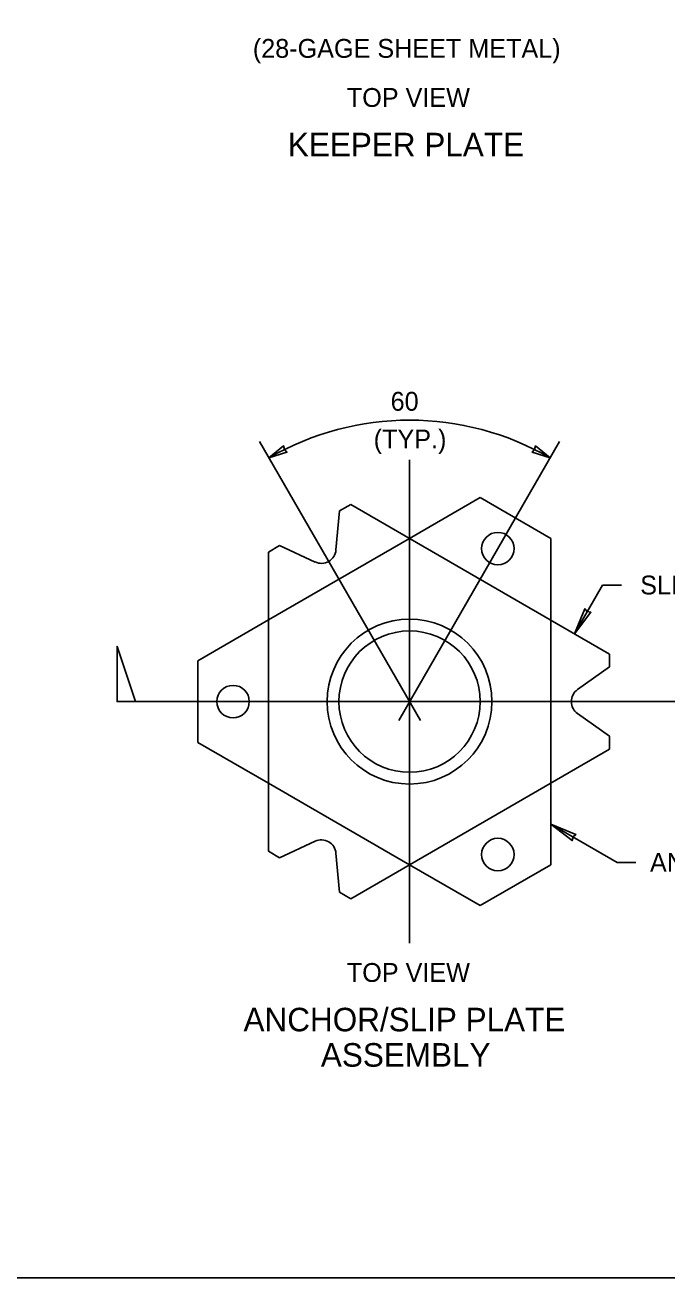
# Model space of a CAD drawing. Extents: x 99862 to 104211, y 98939 to 102076.
# Drawn here: x 100770 to 101315, y 100000 to 101063 of the extents above; entities that cross this region are included whole.
import ezdxf

# ---------------------------------------------------------------- set-up
doc = ezdxf.new("R2010")
doc.units = 0
for name, color, linetype in [('Level 1', 7, 'Continuous'), ('Level 15', 7, 'Continuous'), ('Level 20', 7, 'Continuous'), ('Level 3', 7, 'Continuous'), ('Level 4', 7, 'Continuous'), ('Level 9', 7, 'Continuous')]:
    doc.layers.add(name, color=color, linetype=linetype)

msp = doc.modelspace()

# ---------------------------------------------------------------- linework, layer by layer
at = {"layer": 'Level 1'}
msp.add_lwpolyline([(99862, 99999.5), (103151, 99999.5), (103151, 102075.5), (99862, 102075.5)], close=True, dxfattribs=at)
at = {"layer": 'Level 15'}
for p, q in [((101105.7, 100472.9), (100969, 100709.7)), ((101087.3, 100472.9), (101224, 100709.7)), ((101096.5, 100283.7), (101096.5, 100694.1)), ((101236.6, 100546.5), (101260.5, 100587.9)), ((101260.5, 100587.9), (101276.5, 100587.9)), ((101216.5, 100384.9), (101272.8, 100352.4)), ((101272.8, 100352.4), (101288.8, 100352.4))]:
    msp.add_line(p, q, dxfattribs=at)
for points in [[(100977, 100695.9), (100992.3, 100700.6), (100990.2, 100702.9), (100989.4, 100706)], [(101216, 100695.9), (101200.7, 100700.6), (101202.8, 100702.9), (101203.6, 100706)], [(101236.6, 100546.5), (101245.5, 100567.8), (101247.5, 100565.4), (101250.6, 100564.8)], [(101216.5, 100384.9), (101237.8, 100376.1), (101235.4, 100374.1), (101234.8, 100370.9)]]:
    msp.add_lwpolyline(points, close=True, dxfattribs=at)
msp.add_arc((101096.5, 100488.9), 239, 60, 120, dxfattribs=at)
at = {"layer": 'Level 3'}
for p, q in [((101096.5, 100627.4), (101156.5, 100662.1)), ((101216.5, 100627.4), (101156.5, 100662.1)), ((100976.5, 100558.2), (101096.5, 100627.4)), ((101216.5, 100627.4), (101216.5, 100558.2)), ((100916.5, 100523.5), (100976.5, 100558.2)), ((101216.5, 100558.2), (101216.5, 100419.6)), ((100916.5, 100523.5), (100916.5, 100454.2)), ((100976.5, 100419.6), (100916.5, 100454.2)), ((101096.5, 100350.3), (100976.5, 100419.6)), ((101216.5, 100419.6), (101216.5, 100350.3)), ((101156.5, 100315.7), (101096.5, 100350.3)), ((101156.5, 100315.7), (101216.5, 100350.3))]:
    msp.add_line(p, q, dxfattribs=at)
for centre, radius in [((101171.5, 100618.8), 13.8), ((101096.5, 100488.9), 70), ((100946.5, 100488.9), 13.8), ((101171.5, 100359), 13.8)]:
    msp.add_circle(centre, radius, dxfattribs=at)
at = {"layer": 'Level 4'}
for p, q in [((101036.9, 100650.8), (101046.5, 100656.3)), ((101046.5, 100656.3), (101266.5, 100529.3)), ((101033.9, 100617.7), (101036.9, 100650.8)), ((100976.5, 100615.9), (100986.1, 100621.4)), ((100976.5, 100361.9), (100976.5, 100615.9)), ((100986.1, 100621.4), (101016.2, 100607.4)), ((101266.5, 100529.3), (101266.5, 100518.3)), ((101266.5, 100518.3), (101239.3, 100499.1)), ((101239.3, 100478.7), (101266.5, 100459.5)), ((101266.5, 100459.5), (101266.5, 100448.5)), ((101266.5, 100448.5), (101046.5, 100321.4)), ((101016.2, 100370.3), (100986.1, 100356.3)), ((100986.1, 100356.3), (100976.5, 100361.9)), ((101036.9, 100327), (101033.9, 100360.1)), ((101046.5, 100321.4), (101036.9, 100327))]:
    msp.add_line(p, q, dxfattribs=at)
msp.add_circle((101096.5, 100488.9), 60, dxfattribs=at)
for centre, start, end in [((101021.5, 100618.8), 245.1652, 354.8348), ((101246.5, 100488.9), 125.1652, 234.8348), ((101021.5, 100359), 5.1652, 114.8348)]:
    msp.add_arc(centre, 12.5, start, end, dxfattribs=at)
at = {"layer": 'Level 9'}
msp.add_line((100848, 100488.9), (101329.6, 100488.9), dxfattribs=at)
msp.add_lwpolyline([(100863.5, 100488.9), (100848, 100535.8), (100848, 100488.9)], close=True, dxfattribs=at)

# ---------------------------------------------------------------- texts
at = {"layer": 'Level 20'}
for s, height, p in [('(28-GAGE SHEET METAL)', 16, (100963.3, 101035.6)), ('TOP VIEW', 16, (101043.2, 100993.9)), ('KEEPER PLATE', 20, (100993.1, 100951.9)), ('60', 16, (101080.4, 100735.9)), ('(TYP.)', 16, (101066, 100703.9)), ('SLIP PLATE', 16, (101292.5, 100579.9)), ('TOP VIEW', 16, (101043.2, 100250.9)), ('ANCHOR/SLIP PLATE', 20, (100955.4, 100208.9)), ('ASSEMBLY', 20, (101021.1, 100178.9))]:
    msp.add_text(s, height=height, dxfattribs=at).set_placement(p)
msp.add_text('ANCHOR PLATE', height=16, rotation=360, dxfattribs=at).set_placement((101300.8, 100344.4))

doc.saveas('drawing.dxf')
